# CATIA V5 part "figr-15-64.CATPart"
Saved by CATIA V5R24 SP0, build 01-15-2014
Part number: Part1
Bounding box of the stored display mesh (mm): x -10 to 10, y -10 to 10, z 0 to 26
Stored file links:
  D:\KAVITA\CATIA V5-6R2014 Project_ Kavita\CATIA V5-6R2014_partfiles\Partfiles\c15_catia_v5-6r2014_prt\figr-15-64.CATPart
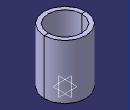
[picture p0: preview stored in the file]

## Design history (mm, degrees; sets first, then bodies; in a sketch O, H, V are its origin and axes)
SheetMetalParameters1: Thickness 2, BendRadius 4, KFactor 0.400515 {= log(min(100,max(20*SheetMetalParameters1.BendRadius,SheetMetalParameters1.Thickness)/SheetMetalParameters1.Thickness))/log(100)/2}, ReliefRadialLength 1, ReliefAxialLength 2, MinimumBendRadius 0
Body1 (main body)
  Sketch1 on xy-plane, origin (0, 0, 0), H (1, 0, 0), V (0, 1, 0)
    circle A1 centre (0, 0) radius 10
    radius A1 = 10
  d_RolledWall1: Extrude_Thickness 2, Extrude_StartLength 26, KFacteur 0.400515 {= SheetMetalParameters1.KFactor}, Extrude_EndLength 0, RolledWall_DeductionTable SheetMetalParameters1, Extrude_Profile Sketch1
